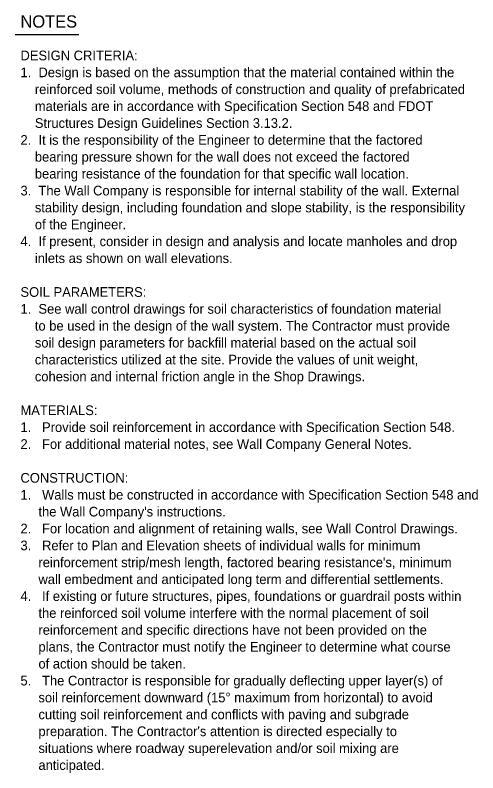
# Model space of a CAD drawing. Extents: x 126777.1 to 126780.68, y 176294.14 to 176295.44.
# Drawn here: x 126778.4578 to 126778.7591, y 176294.8637 to 176295.357 of the extents above; entities that cross this region are included whole.
import ezdxf

# ---------------------------------------------------------------- set-up
doc = ezdxf.new("R2010")
doc.units = 0
doc.layers.add('AdhocPoint_dp', color=7, linetype='Continuous')
doc.layers.add('TextMisc', color=7, linetype='Continuous')

msp = doc.modelspace()

# ---------------------------------------------------------------- linework, layer by layer
at = {"layer": 'AdhocPoint_dp'}
msp.add_line((126778.45784, 176295.34438), (126778.4993, 176295.34438), dxfattribs=at)

# ---------------------------------------------------------------- texts
at = {"layer": 'TextMisc'}
for s, height, p in [('NOTES', 0.008, (126778.4613, 176295.34887)), ('DESIGN CRITERIA:', 0.0063, (126778.4613, 176295.32761)), ('1.  Design is based on the assumption that the material contained within the', 0.0063, (126778.4613, 176295.31661)), ('    reinforced soil volume, methods of construction and quality of prefabricated', 0.0063, (126778.4613, 176295.30561)), ('    materials are in accordance with Specification Section 548 and FDOT ', 0.0063, (126778.4613, 176295.29461)), ('    Structures Design Guidelines Section 3.13.2.', 0.0063, (126778.4613, 176295.28361)), ('2.  It is the responsibility of the Engineer to determine that the factored', 0.0063, (126778.4613, 176295.27261)), ('    bearing pressure shown for the wall does not exceed the factored', 0.0063, (126778.4613, 176295.26161)), ('    bearing resistance of the foundation for that specific wall location.', 0.0063, (126778.4613, 176295.25061)), ('3.  The Wall Company is responsible for internal stability of the wall. External', 0.0063, (126778.4613, 176295.23961)), ('    stability design, including foundation and slope stability, is the responsibility', 0.0063, (126778.4613, 176295.22861)), ('    of the Engineer.', 0.0063, (126778.4613, 176295.21761)), ('4.  If present, consider in design and analysis and locate manholes and drop', 0.0063, (126778.4613, 176295.20661)), ('    inlets as shown on wall elevations.', 0.0063, (126778.4613, 176295.19561)), ('SOIL PARAMETERS:', 0.0063, (126778.4613, 176295.17361)), ('1.  See wall control drawings for soil characteristics of foundation material', 0.0063, (126778.4613, 176295.16261)), ('    to be used in the design of the wall system. The Contractor must provide', 0.0063, (126778.4613, 176295.15161)), ('    soil design parameters for backfill material based on the actual soil', 0.0063, (126778.4613, 176295.14061)), ('    characteristics utilized at the site. Provide the values of unit weight,', 0.0063, (126778.4613, 176295.12961)), ('    cohesion and internal friction angle in the Shop Drawings.', 0.0063, (126778.4613, 176295.11861)), ('MATERIALS:', 0.0063, (126778.4613, 176295.09661)), ('1.   Provide soil reinforcement in accordance with Specification Section 548.', 0.0063, (126778.4613, 176295.08561)), ('2.   For additional material notes, see Wall Company General Notes.', 0.0063, (126778.4613, 176295.07461)), ('CONSTRUCTION:', 0.0063, (126778.4613, 176295.05261)), ('1.   Walls must be constructed in accordance with Specification Section 548 and', 0.0063, (126778.4613, 176295.04161)), ("     the Wall Company's instructions.", 0.0063, (126778.4613, 176295.03061)), ('2.   For location and alignment of retaining walls, see Wall Control Drawings.', 0.0063, (126778.4613, 176295.01961)), ('3.   Refer to Plan and Elevation sheets of individual walls for minimum', 0.0063, (126778.4613, 176295.00861)), ("     reinforcement strip/mesh length, factored bearing resistance's, minimum", 0.0063, (126778.4613, 176294.99761)), ('     wall embedment and anticipated long term and differential settlements.', 0.0063, (126778.4613, 176294.98661)), ('4.   If existing or future structures, pipes, foundations or guardrail posts within', 0.0063, (126778.4613, 176294.97561)), ('     the reinforced soil volume interfere with the normal placement of soil', 0.0063, (126778.4613, 176294.96461)), ('     reinforcement and specific directions have not been provided on the', 0.0063, (126778.4613, 176294.95361)), ('     plans, the Contractor must notify the Engineer to determine what course', 0.0063, (126778.4613, 176294.94261)), ('     of action should be taken.', 0.0063, (126778.4613, 176294.93161)), ('5.   The Contractor is responsible for gradually deflecting upper layer(s) of', 0.0063, (126778.4613, 176294.92061)), ('     soil reinforcement downward (15° maximum from horizontal) to avoid', 0.0063, (126778.4613, 176294.90961)), ('     cutting soil reinforcement and conflicts with paving and subgrade', 0.0063, (126778.4613, 176294.89861)), ("     preparation. The Contractor's attention is directed especially to", 0.0063, (126778.4613, 176294.88761)), ('     situations where roadway superelevation and/or soil mixing are', 0.0063, (126778.4613, 176294.87661)), ('     anticipated.', 0.0063, (126778.4613, 176294.86561))]:
    msp.add_text(s, height=height, dxfattribs=at).set_placement(p)

doc.saveas('drawing.dxf')
